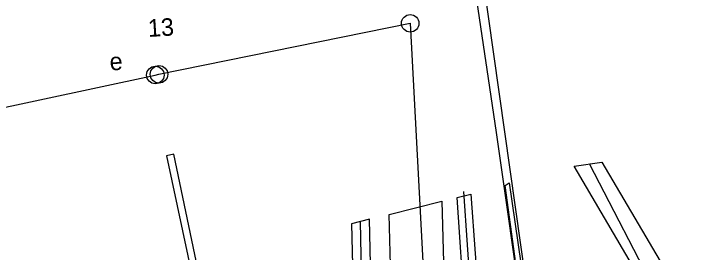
# Model space of a CAD drawing. Extents: x 738423 to 738903, y 6589762 to 6590172.
# Drawn here: x 738714.1 to 738792, y 6590008 to 6590035.2 of the extents above; entities that cross this region are included whole.
import ezdxf

# ---------------------------------------------------------------- set-up
doc = ezdxf.new("R2010")
doc.units = 0
for name, color, linetype in [('_1927_hoonestus', 7, 'Continuous'), ('_1927_koordin_punktid_nr', 7, 'Continuous'), ('_1927_krundi_piir', 7, 'Continuous'), ('a_kaitsealune_park', 7, 'Continuous'), ('v_dp_jalak_liikumine', 7, 'Continuous'), ('v_olol_kivimuur', 7, 'Continuous'), ('v_olol_transp_jjt_jalg', 7, 'Continuous'), ('v_olol_transp_tee', 7, 'Continuous')]:
    doc.layers.add(name, color=color, linetype=linetype)

msp = doc.modelspace()

# ---------------------------------------------------------------- linework, layer by layer
at = {"layer": '_1927_hoonestus'}
msp.add_lwpolyline([(738700.414, 6589980.608), (738701.767, 6589980.951), (738701.546, 6589981.949), (738738.467, 6589990.441), (738732.441, 6590019.185), (738731.608, 6590019.01), (738737.593, 6589990.974), (738699.944, 6589982.509)], close=True, dxfattribs=at)
at = {"layer": '_1927_koordin_punktid_nr'}
for centre in [(738759.446, 6590034.134), (738730.327, 6590028.224), (738730.742, 6590028.31)]:
    msp.add_circle(centre, 1, dxfattribs=at)
at = {"layer": '_1927_krundi_piir'}
msp.add_lwpolyline([(738765.881, 6590052.439), (738773.315, 6589999.959), (738784.779, 6590001.213)], dxfattribs=at)
msp.add_lwpolyline([(738708.45, 6589948.12), (738700.042, 6589982.114), (738690.737, 6590019.738), (738730.327, 6590028.224), (738730.742, 6590028.31), (738759.446, 6590034.134), (738761.505, 6589995.407), (738758.078, 6589946.139)], close=True, dxfattribs=at)
at = {"layer": 'a_kaitsealune_park'}
msp.add_lwpolyline([(738799.76, 6589792.27), (738785.86, 6589778.87), (738784.7, 6589778.87), (738782.88, 6589779.53), (738781.39, 6589772.74), (738771.13, 6589773.57), (738772.78, 6589780.85), (738773.44, 6589784.33), (738773.94, 6589792.27), (738774.27, 6589803.03), (738773.78, 6589812.8), (738772.78, 6589869.23), (738770.47, 6589904.48), (738769.8, 6589927.49), (738768.64, 6589952.32), (738783.87, 6590000.64), (738772.45, 6589999.48), (738769.31, 6590021.66), (738764.34, 6590055.09)], dxfattribs=at)
msp.add_lwpolyline([(738799.76, 6589792.27), (738785.86, 6589778.87), (738784.7, 6589778.87), (738782.88, 6589779.53), (738781.39, 6589772.74), (738771.13, 6589773.57), (738772.78, 6589780.85), (738773.44, 6589784.33), (738773.94, 6589792.27), (738774.27, 6589803.03), (738773.78, 6589812.8), (738772.78, 6589869.23), (738770.47, 6589904.48), (738769.8, 6589927.49), (738768.64, 6589952.32), (738783.87, 6590000.64), (738772.45, 6589999.48), (738769.31, 6590021.66), (738764.34, 6590055.09)], dxfattribs=at)
at = {"layer": 'v_dp_jalak_liikumine'}
for points in [[(738767.725, 6590000.521), (738780.096, 6590001.74), (738787.789, 6590002.853), (738779.908, 6590018.064)], [(738772.831, 6589822.054), (738772.133, 6589857.589), (738770.962, 6589879.068), (738769.876, 6589900.994), (738769.028, 6589927.12), (738768.175, 6589945.034), (738767.995, 6589954.494), (738767.592, 6589970.545), (738766.417, 6590002.737), (738765.569, 6590014.936)], [(738753.735, 6590011.485), (738754.549, 6589968.543), (738755.466, 6589938.815), (738757.049, 6589902.977), (738757.75, 6589889.633), (738760.396, 6589885.01), (738760.656, 6589876.988), (738761.057, 6589862.973), (738761.398, 6589851.105), (738761.791, 6589844.08)]]:
    msp.add_lwpolyline(points, dxfattribs=at)
at = {"layer": 'v_olol_kivimuur'}
msp.add_lwpolyline([(738770.281, 6590015.607), (738770.762, 6590015.903), (738772.773, 6590002.026), (738773.923, 6590002.104), (738773.979, 6590001.573), (738772.234, 6590001.402), (738770.281, 6590015.607)], close=True, dxfattribs=at)
at = {"layer": 'v_olol_transp_jjt_jalg'}
for points in [[(738785.111, 6590006.008), (738778.192, 6590017.821), (738781.34, 6590018.267), (738786.748, 6590009.078), (738789.629, 6590004.188)], [(738765.696, 6590001.197), (738764.807, 6590014.238), (738766.372, 6590014.63), (738767.372, 6590001.054)], [(738756.356, 6589953.212), (738755.399, 6589984.344), (738754.777, 6590011.746), (738752.749, 6590011.238), (738753.398, 6589984.476), (738754.325, 6589953.164)]]:
    msp.add_lwpolyline(points, dxfattribs=at)
at = {"layer": 'v_olol_transp_tee'}
msp.add_lwpolyline([(738757.026, 6590012.291), (738763.05, 6590013.817), (738763.91, 6589983.149), (738764.929, 6589952.458), (738765.481, 6589931.863), (738766.166, 6589909.861), (738766.702, 6589890.621), (738767.857, 6589856.708), (738768.121, 6589848.194), (738768.804, 6589822.632), (738762.829, 6589823.608), (738762.238, 6589844.466), (738761.596, 6589867.023), (738760.812, 6589889.301), (738760.214, 6589908.839), (738759.598, 6589929.525), (738758.859, 6589952.365), (738757.828, 6589984.57), (738757.361, 6590000.717)], close=True, dxfattribs=at)

# ---------------------------------------------------------------- texts
at = {"layer": '_1927_koordin_punktid_nr'}
for s, p in [('13', (738729.539, 6590032.568)), ('e', (738725.162, 6590028.737))]:
    msp.add_text(s, height=2, rotation=3.56086, dxfattribs=at).set_placement(p)

doc.saveas('drawing.dxf')
